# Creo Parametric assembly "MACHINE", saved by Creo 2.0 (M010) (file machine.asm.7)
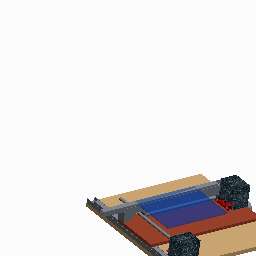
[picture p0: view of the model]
Units: Inch lbm Second (Pro/E Default); INCH, POUND, SECS

Created from: INLBS_ASM_DESIGN.ASM

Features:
  1. datum plane "ASM_RIGHT"
  2. datum plane "ASM_TOP"
  3. datum plane "ASM_FRONT"
  4. coordinate system
  5. component "BASE_BOARD"
  6. component "TOPBOARD"
  7. component "YMOTOR"
  8. component "MOTOR"
  9. component "PRT0001"
  10. component "SLIDE_TOP"
  11. component "THREADM6"
  12. component "SKATEBEARING"
  13. component "X_RAISER"
  14. component "PRT0001"
  15. component "SLIDE_TOP"
  16. component "MOTOR"
  17. component "YMOTOR"
  18. component "THREADM6"
  19. component "BED"

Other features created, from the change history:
  component "YMOTOR.PRT"
  component "BASE_BOARD.PRT"
  component "TOPBOARD.PRT"
  component "SKATEBEARING.PRT"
